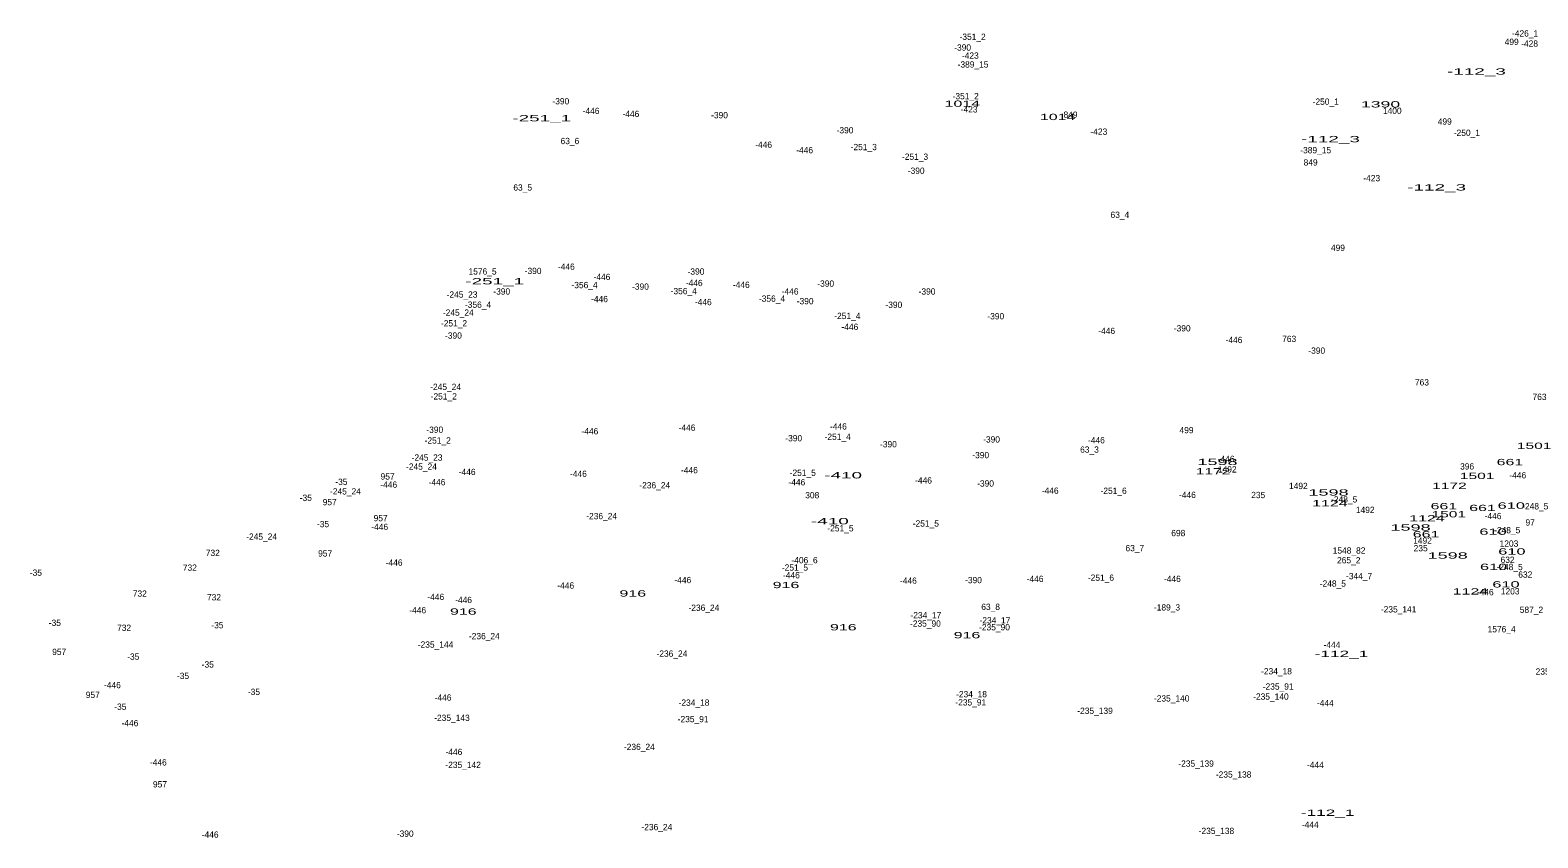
# Model space of a CAD drawing. Extents: x -660434 to -656144, y -997850 to -994016.
# Drawn here: x -660434 to -659474, y -995557 to -995043 of the extents above; entities that cross this region are included whole.
import ezdxf
from ezdxf.enums import TextEntityAlignment as Align

# ---------------------------------------------------------------- set-up
doc = ezdxf.new("R2010")
doc.units = 0
doc.header["$LTSCALE"] = 1.6
doc.layers.add('24', color=7, linetype='Continuous')

msp = doc.modelspace()

# ---------------------------------------------------------------- texts
at = {"layer": '24'}
for s, p in [('-390', (-659840.214, -995056.45)), ('-351_2', (-659833.856, -995049.58)), ('499', (-659490.703, -995052.85)), ('-426_1', (-659482.166, -995047.47)), ('-428', (-659479.309, -995053.94)), ('-423', (-659835.319, -995061.58)), ('-389_15', (-659833.581, -995067.21)), ('-390', (-660095.974, -995090.64)), ('-351_2', (-659838.276, -995087.42)), ('-250_1', (-659609.08, -995090.88)), ('-446', (-660076.739, -995096.77)), ('-446', (-660051.399, -995098.69)), ('-390', (-659994.974, -995099.47)), ('-423', (-659836.079, -995095.77)), ('849', (-659771.517, -995099.18)), ('1400', (-659566.722, -995096.69)), ('499', (-659533.323, -995103.55)), ('-390', (-659915.094, -995109.08)), ('-423', (-659753.519, -995109.98)), ('-250_1', (-659519.22, -995110.68)), ('63_6', (-660090.216, -995115.92)), ('-446', (-659966.909, -995118.28)), ('-446', (-659940.799, -995121.74)), ('-251_3', (-659903.146, -995119.76)), ('-389_15', (-659615.461, -995121.76)), ('-251_3', (-659870.506, -995125.91)), ('849', (-659618.677, -995129.53)), ('-390', (-659869.784, -995134.82)), ('-423', (-659579.789, -995139.53)), ('63_5', (-660120.27, -995145.5)), ('63_4', (-659740.104, -995162.85)), ('499', (-659601.293, -995183.84)), ('1576_5', (-660145.81, -995198.9)), ('-390', (-660113.634, -995198.59)), ('-446', (-660092.489, -995195.88)), ('-390', (-660009.954, -995198.97)), ('-356_4', (-660080.902, -995207.57)), ('-446', (-660069.829, -995202.41)), ('-390', (-660045.284, -995208.58)), ('-446', (-660011.079, -995206.25)), ('-446', (-659981.119, -995207.4)), ('-390', (-659927.384, -995206.65)), ('-245_23', (-660158.876, -995213.6)), ('-390', (-660133.604, -995211.65)), ('-446', (-660071.369, -995216.47)), ('-356_4', (-660017.742, -995211.41)), ('-446', (-660005.319, -995218.39)), ('-356_4', (-659961.552, -995216.21)), ('-446', (-659950.019, -995211.63)), ('-390', (-659940.454, -995217.8)), ('-390', (-659862.874, -995211.65)), ('-245_24', (-660161.28, -995225.12)), ('-356_4', (-660148.682, -995220.05)), ('-251_4', (-659913.61, -995227.24)), ('-390', (-659884.004, -995220.11)), ('-390', (-659819.104, -995227.41)), ('-251_2', (-660163.986, -995231.91)), ('-446', (-659911.999, -995234.14)), ('-446', (-659748.519, -995236.75)), ('-390', (-659700.444, -995235.09)), ('-390', (-660164.324, -995239.7)), ('-446', (-659667.489, -995242.52)), ('763', (-659632.328, -995241.81)), ('-390', (-659614.804, -995249.3)), ('-245_24', (-660169.34, -995272.37)), ('763', (-659547.838, -995269.47)), ('-251_2', (-660170.516, -995278.4)), ('763', (-659472.958, -995278.69)), ('-390', (-660176.234, -995299.62)), ('-446', (-660077.509, -995300.6)), ('-446', (-660015.679, -995298.3)), ('-390', (-659947.744, -995305.01)), ('-251_4', (-659919.76, -995304.07)), ('-446', (-659919.289, -995297.53)), ('-390', (-659821.794, -995305.78)), ('499', (-659697.683, -995299.86)), ('-251_2', (-660174.356, -995306.44)), ('-390', (-659887.454, -995308.85)), ('-390', (-659828.704, -995315.76)), ('63_3', (-659759.46, -995312.28)), ('-446', (-659755.049, -995306.29)), ('-245_24', (-660184.7, -995323.08)), ('-245_23', (-660181.146, -995317.32)), ('-446', (-660014.109, -995325.33)), ('-446', (-659672.489, -995318.2)), ('1492', (-659671.76, -995324.84)), ('396', (-659519.068, -995322.94)), ('-35', (-660235.665, -995332.76)), ('-446', (-660205.539, -995334.55)), ('957', (-660206.268, -995329.35)), ('-446', (-660174.819, -995333.01)), ('-446', (-660155.619, -995326.48)), ('-446', (-660084.769, -995327.64)), ('-236_24', (-660036.211, -995334.96)), ('-446', (-659945.749, -995333.02)), ('-251_5', (-659941.976, -995326.99)), ('-446', (-659865.109, -995331.87)), ('-390', (-659825.624, -995333.82)), ('-446', (-659486.809, -995328.57)), ('-35', (-660258.325, -995342.93)), ('-245_24', (-660233.09, -995338.83)), ('308', (-659935.941, -995341.28)), ('-446', (-659784.469, -995338.4)), ('-251_6', (-659744.102, -995338.44)), ('-446', (-659697.099, -995341.09)), ('235', (-659652.067, -995341.16)), ('1492', (-659626.5, -995335.4)), ('-248_5', (-659597.337, -995343.92)), ('957', (-660243.138, -995345.67)), ('1492', (-659583.93, -995350.58)), ('-248_5', (-659475.697, -995348.34)), ('-35', (-660247.385, -995359.64)), ('-446', (-660211.299, -995361.44)), ('957', (-660210.688, -995355.85)), ('-236_24', (-660070.001, -995354.55)), ('-251_5', (-659917.976, -995362.33)), ('-251_5', (-659863.636, -995359.25)), ('-446', (-659502.559, -995354.53)), ('-248_5', (-659493.557, -995363.51)), ('97', (-659478.938, -995358.6)), ('-245_24', (-660286.46, -995367.64)), ('698', (-659702.928, -995365.35)), ('1492', (-659547.45, -995370.17)), ('1203', (-659492.444, -995372.06)), ('732', (-660317.543, -995377.97)), ('957', (-660246.018, -995378.32)), ('-406_6', (-659940.852, -995382.6)), ('63_7', (-659730.596, -995374.95)), ('1548_82', (-659594.222, -995376.44)), ('265_2', (-659594.42, -995382.66)), ('235', (-659548.647, -995375)), ('632', (-659493.313, -995382.34)), ('-35', (-660430.175, -995390.56)), ('732', (-660332.133, -995387.38)), ('-446', (-660202.089, -995384.11)), ('-251_5', (-659946.966, -995387.3)), ('-446', (-659949.209, -995392.18)), ('-248_5', (-659492.017, -995386.95)), ('632', (-659482.033, -995391.78)), ('-446', (-660092.829, -995398.71)), ('-446', (-660018.329, -995395.25)), ('-446', (-659874.709, -995395.64)), ('-390', (-659833.304, -995395.28)), ('-446', (-659794.069, -995394.49)), ('-251_6', (-659752.172, -995393.76)), ('-446', (-659706.699, -995394.49)), ('-248_5', (-659604.547, -995397.51)), ('-344_7', (-659587.816, -995392.74)), ('732', (-660364.003, -995403.9)), ('732', (-660316.773, -995406.21)), ('-446', (-660175.589, -995406)), ('-446', (-660157.919, -995407.93)), ('-446', (-659507.549, -995402.94)), ('1203', (-659491.674, -995402.41)), ('-446', (-660187.109, -995414.46)), ('-236_24', (-660004.911, -995412.87)), ('-234_17', (-659863.615, -995417.64)), ('-234_17', (-659819.645, -995420.9)), ('63_8', (-659822.39, -995412.28)), ('-189_3', (-659710.122, -995412.65)), ('-235_141', (-659562.683, -995413.9)), ('587_2', (-659478.12, -995414.18)), ('-35', (-660418.075, -995422.45)), ('732', (-660373.993, -995425.61)), ('-35', (-660314.585, -995423.99)), ('-236_24', (-660144.691, -995430.93)), ('-235_90', (-659863.911, -995422.95)), ('-235_90', (-659819.911, -995425.28)), ('1576_4', (-659497.094, -995426.54)), ('-235_144', (-660175.754, -995436.3)), ('-444', (-659605.107, -995436.45)), ('957', (-660415.308, -995440.94)), ('-35', (-660368.155, -995443.97)), ('-35', (-660320.725, -995448.96)), ('-236_24', (-660025.261, -995442.07)), ('-35', (-660336.475, -995456.26)), ('-234_18', (-659640.409, -995453.29)), ('235', (-659470.977, -995453.46)), ('957', (-660393.918, -995468.28)), ('-446', (-660381.419, -995462.09)), ('-35', (-660291.355, -995466.43)), ('-234_18', (-659834.569, -995467.88)), ('-235_91', (-659639.351, -995463)), ('-35', (-660376.415, -995475.85)), ('-446', (-660170.979, -995470.01)), ('-234_18', (-660011.209, -995473.26)), ('-235_91', (-659835.031, -995473.08)), ('-235_139', (-659755.931, -995478.43)), ('-235_140', (-659707.143, -995470.55)), ('-235_140', (-659643.973, -995469.4)), ('-444', (-659609.337, -995473.52)), ('-446', (-660370.289, -995486.29)), ('-235_143', (-660165.289, -995482.9)), ('-235_91', (-660011.771, -995483.74)), ('-446', (-660164.069, -995504.59)), ('-236_24', (-660046.001, -995501.41)), ('-446', (-660352.239, -995511.26)), ('-235_142', (-660158.179, -995512.83)), ('-235_139', (-659691.601, -995512.04)), ('-444', (-659615.667, -995512.89)), ('957', (-660351.178, -995525.22)), ('-235_138', (-659667.705, -995518.95)), ('-236_24', (-660034.861, -995552.42)), ('-235_138', (-659678.645, -995554.87)), ('-444', (-659618.937, -995550.92)), ('-446', (-660319.209, -995557.22)), ('-390', (-660195.044, -995556.62))]:
    msp.add_text(s, height=4, dxfattribs=at).set_placement(p, align=Align.CENTER)
for s, width, p in [('-112_3', 2.25, (-659513.137, -995071.67)), ('1014', 1.9, (-659840.406, -995092.17)), ('1390', 2.1, (-659574.189, -995092.59)), ('-251_1', 2.25, (-660108.117, -995101.42)), ('1014', 1.9, (-659779.736, -995100.62)), ('-112_3', 2.25, (-659606.067, -995114.69)), ('-112_3', 2.25, (-659538.477, -995145.42)), ('-251_1', 2.25, (-660138.067, -995205.15)), ('1501', 1.85, (-659476.4, -995309.81)), ('1598', 2.15, (-659677.963, -995320.11)), ('661', 1.9, (-659491.817, -995320.19)), ('-410', 2.25, (-659916.282, -995328.61)), ('1172', 1.85, (-659680.839, -995326.08)), ('1501', 1.85, (-659512.69, -995329.02)), ('1598', 2.15, (-659607.303, -995339.51)), ('1172', 1.85, (-659530.309, -995335.3)), ('1124', 1.9, (-659606.459, -995346.39)), ('661', 1.9, (-659533.867, -995348.24)), ('1501', 1.85, (-659530.74, -995353.39)), ('661', 1.9, (-659509.287, -995349.39)), ('610', 1.95, (-659490.969, -995347.87)), ('-410', 2.25, (-659924.722, -995357.8)), ('1598', 2.15, (-659555.083, -995361.8)), ('1124', 1.9, (-659544.639, -995355.99)), ('661', 1.9, (-659545.197, -995366.1)), ('610', 1.95, (-659502.579, -995364.48)), ('1598', 2.15, (-659531.463, -995379.66)), ('610', 1.95, (-659490.579, -995377.06)), ('610', 1.95, (-659502.199, -995386.86)), ('916', 1.9, (-659952.647, -995398.41)), ('610', 1.95, (-659494.329, -995398)), ('916', 1.9, (-660050.187, -995403.79)), ('1124', 1.9, (-659516.989, -995402.47)), ('916', 1.9, (-660158.087, -995415.31)), ('916', 1.9, (-659916.167, -995425.3)), ('916', 1.9, (-659837.437, -995430.3)), ('-112_1', 2.05, (-659599.044, -995442.25)), ('-112_1', 2.05, (-659607.874, -995543.29))]:
    msp.add_text(s, height=4, dxfattribs=dict(at, width=width)).set_placement(p, align=Align.CENTER)

doc.saveas('drawing.dxf')
